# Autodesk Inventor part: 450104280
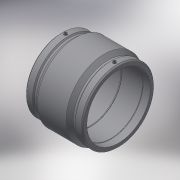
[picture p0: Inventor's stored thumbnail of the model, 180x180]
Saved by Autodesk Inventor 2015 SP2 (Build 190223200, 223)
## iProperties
Created: 2017-06
Part Number: 450104280
Material: Generic
Description: PLASSON COUPLER 280 PN25
Document SubType Name: Modeling
Designer: KIM
Mass: 8622.19 g
Surface Area: 6772.47 cm^2
Volume: 8622.19 cm^3
Density: 1 g/cm^3
Appearance: Default
Author: KIM
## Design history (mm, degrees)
derived "450104.ipt"
feature "Solid1::450104.ipt"
tag "TaggingFeature1"
body "Solid1"
other parameters: "d0" = 274, "d2" = 341, "d3" = 135, "d4" = 68.5, "d5" = 306.9, "d6" = 224, "d8" = 168 deg, "d10" = 54, "d11" = 18, "d13" = 274, "d14" = 17.6296, "d15" = 135, "d16" = 135, "d17" = 277.2, "d19" = 3.52592, "d20" = 168 deg, "d22" = 320.54, "d23" = 341, "d24" = 310.9238, "d25" = 135 deg, "d26" = 137, "d27" = 135 deg, "d29" = 166, "d30" = 15, "d31" = 95.9, "d34" = 5 deg, "d35" = 15, "d39" = 5 deg, "d41" = 4, "d42" = 14, "d43" = 0, "d45" = 4, "d46" = 14, "d47" = 0, "d48" = 3, "d49" = 0, "d50" = 3, "d51" = 0, "d52" = 39.15, "d53" = 9.7875, "L_" = 274, "L_1" = 135, "D_" = 341, "A_" = 166, "d_2" = 12
